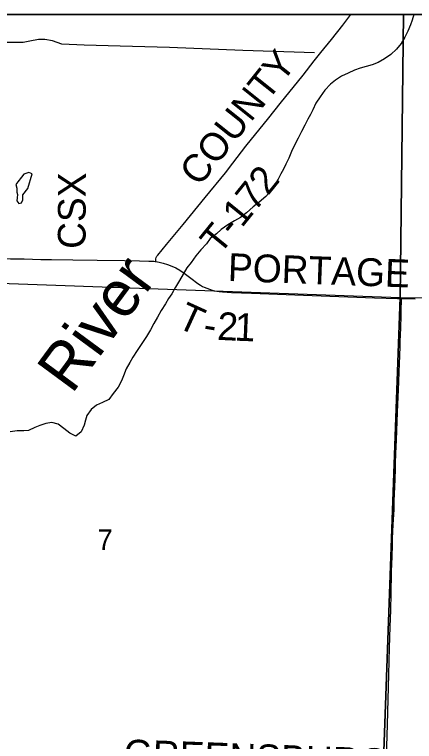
# Model space of a CAD drawing. Extents: x 0 to 39.4, y 0 to 22.
# Drawn here: x 5.679 to 6.495, y 19.416 to 20.9 of the extents above; entities that cross this region are included whole.
import ezdxf

# ---------------------------------------------------------------- set-up
doc = ezdxf.new("R2010")
doc.units = 0
for name, color, linetype in [('Default', 7, 'Continuous'), ('GM_X_Interstate_Route', 7, 'Continuous'), ('GM_X_Major_River', 7, 'Continuous'), ('GM_X_Minor_Lake', 7, 'Continuous'), ('GM_X_Minor_River', 7, 'Continuous'), ('GM_X_Minor_River_Text', 7, 'Continuous'), ('GM_X_Rail_Line_Text', 7, 'Continuous'), ('GM_X_Section', 7, 'Continuous'), ('GM_X_Section_Text', 7, 'Continuous'), ('GM_X_Township_Road', 7, 'Continuous'), ('GM_X_Township_Road_Text', 7, 'Continuous'), ('SH_Data', 7, 'Continuous')]:
    doc.layers.add(name, color=color, linetype=linetype)

msp = doc.modelspace()

# ---------------------------------------------------------------- linework, layer by layer
at = {"layer": 'Default'}
for points in [[(6.4727, 20.9), (5.4307, 20.9), (5.4199, 20.4099), (5.4196, 20.3595), (6.4661, 20.3227)], [(7.4771, 20.9), (6.4727, 20.9), (6.4661, 20.3227), (7.4647, 20.3092)]]:
    msp.add_lwpolyline(points, close=True, dxfattribs=at)
at = {"layer": 'GM_X_Interstate_Route'}
msp.add_lwpolyline([(8.9, 20.9), (5.4327, 20.9)], dxfattribs=at)
at = {"layer": 'GM_X_Major_River'}
for points in [[(6.494, 20.9), (6.4907, 20.8888), (6.4873, 20.8793), (6.4819, 20.866), (6.4758, 20.8539), (6.4682, 20.841), (6.4587, 20.8292), (6.4473, 20.8186), (6.4343, 20.8095), (6.4214, 20.8024), (6.4093, 20.7975), (6.3971, 20.7941), (6.3846, 20.7907), (6.3728, 20.7866), (6.3599, 20.7805), (6.3462, 20.7741), (6.334, 20.7658), (6.3238, 20.7578), (6.3124, 20.7453), (6.3028, 20.7321), (6.2941, 20.7192), (6.2879, 20.7055), (6.2834, 20.696), (6.278, 20.6865), (6.2712, 20.674), (6.2647, 20.6615), (6.2578, 20.6475), (6.2505, 20.6334), (6.244, 20.6202), (6.2387, 20.6065), (6.233, 20.5944), (6.228, 20.5845), (6.2227, 20.5746), (6.2169, 20.564), (6.2093, 20.5519), (6.2032, 20.5417), (6.1922, 20.5284), (6.1781, 20.517), (6.1663, 20.5072), (6.1522, 20.4955), (6.14, 20.486), (6.1279, 20.4788), (6.1142, 20.4709), (6.1009, 20.4614), (6.0914, 20.4527), (6.0781, 20.4429), (6.0704, 20.4319), (6.0594, 20.4198), (6.0491, 20.4073), (6.0392, 20.394), (6.0308, 20.383), (6.0232, 20.3697), (6.0156, 20.3568), (6.0076, 20.3436), (5.9999, 20.3299), (5.9931, 20.3201), (5.987, 20.3094), (5.9778, 20.2962), (5.9706, 20.2825), (5.9633, 20.2692), (5.9564, 20.2567), (5.9481, 20.2431), (5.9385, 20.2287), (5.929, 20.2143), (5.9202, 20.2006), (5.9141, 20.19), (5.9065, 20.1771), (5.9011, 20.1623), (5.8969, 20.1525), (5.8901, 20.1396), (5.8802, 20.1267), (5.871, 20.1145), (5.8585, 20.1081), (5.8463, 20.1028)], [(5.8463, 20.1028), (5.8353, 20.0941), (5.8265, 20.0813), (5.8234, 20.0718), (5.8211, 20.0615), (5.815, 20.0482), (5.804, 20.0395), (5.7915, 20.0453), (5.7794, 20.0548), (5.7676, 20.064), (5.7548, 20.0674), (5.7426, 20.0652), (5.7301, 20.061), (5.7202, 20.0569), (5.7073, 20.0508), (5.6978, 20.0505), (5.6841, 20.0502), (5.6701, 20.0479)]]:
    msp.add_lwpolyline(points, dxfattribs=at)
at = {"layer": 'GM_X_Minor_Lake'}
msp.add_line((5.6834, 20.5371), (5.6845, 20.5325), dxfattribs=at)
msp.add_lwpolyline([(5.6845, 20.5325), (5.6841, 20.5257), (5.6837, 20.52), (5.6875, 20.5143), (5.6928, 20.5158), (5.6959, 20.5215), (5.6959, 20.5321), (5.7058, 20.545), (5.7146, 20.5746), (5.7078, 20.5773), (5.6979, 20.5739), (5.693, 20.5678), (5.6857, 20.5584), (5.6815, 20.5531), (5.6834, 20.5458), (5.6834, 20.5371)], dxfattribs=at)
at = {"layer": 'GM_X_Minor_River'}
msp.add_lwpolyline([(6.291, 20.8217), (6.1449, 20.8264), (5.9954, 20.8329), (5.8941, 20.8354), (5.8209, 20.8376), (5.7754, 20.8392), (5.7655, 20.8427), (5.756, 20.8465), (5.7405, 20.8492), (5.7276, 20.8488), (5.7097, 20.8455), (5.6961, 20.8429), (5.6767, 20.8429), (5.6574, 20.843), (5.6471, 20.8472), (5.6142, 20.8568), (5.5831, 20.8607), (5.5531, 20.8592), (5.5083, 20.8616), (5.4541, 20.8614)], dxfattribs=at)
at = {"layer": 'GM_X_Section'}
for points in [[(5.4196, 20.3595), (6.4661, 20.3227), (6.4302, 19.3208), (5.4065, 19.3604), (5.4059, 19.4006)], [(6.4661, 20.3227), (7.4647, 20.3092), (7.439, 19.3083), (6.4302, 19.3208)]]:
    msp.add_lwpolyline(points, close=True, dxfattribs=at)
at = {"layer": 'GM_X_Township_Road'}
msp.add_line((6.469, 20.3205), (6.4968, 20.3199), dxfattribs=at)
for points in [[(5.967, 20.3961), (5.9672, 20.3995), (5.9675, 20.4016), (5.9682, 20.4039), (5.9695, 20.4066), (5.9714, 20.4091), (5.9891, 20.4307), (6.0228, 20.4713), (6.0683, 20.5264), (6.1092, 20.5772), (6.1245, 20.5968), (6.1513, 20.631), (6.198, 20.6891), (6.2213, 20.7181), (6.2678, 20.7764), (6.2909, 20.8057), (6.3044, 20.8227), (6.3258, 20.8493), (6.3488, 20.8786), (6.3657, 20.9)], [(5.5479, 20.4032), (5.5743, 20.4028), (5.6115, 20.4022), (5.6394, 20.4019), (5.6704, 20.4014), (5.6983, 20.4011), (5.7324, 20.4002), (5.7541, 20.3999), (5.7976, 20.3994), (5.8472, 20.3987), (5.903, 20.398), (5.934, 20.3972), (5.9528, 20.3969)], [(5.9528, 20.3969), (5.9588, 20.3969), (5.9632, 20.3966), (5.9661, 20.3962), (5.967, 20.3961)], [(5.967, 20.3961), (5.9704, 20.3955), (5.9742, 20.3946), (5.9819, 20.3924), (5.9909, 20.3898), (5.9997, 20.3865), (6.0083, 20.3827), (6.0165, 20.3781), (6.0252, 20.3721), (6.0386, 20.3621), (6.0529, 20.3512), (6.0585, 20.3474), (6.0627, 20.345), (6.0657, 20.3435), (6.0712, 20.3412), (6.0766, 20.3391), (6.0821, 20.3375), (6.088, 20.3359), (6.0916, 20.3353), (6.0966, 20.3346), (6.1033, 20.334), (6.1219, 20.3329), (6.1623, 20.3314), (6.2865, 20.3265), (6.4139, 20.3219), (6.4605, 20.3207), (6.469, 20.3205)], [(6.4505, 19.8203), (6.4508, 19.8308), (6.4522, 19.8588), (6.4537, 19.8898), (6.4543, 19.9078), (6.4547, 19.9208), (6.4557, 19.9512), (6.4565, 19.9736), (6.4568, 19.9829), (6.4576, 20.0047), (6.4587, 20.0314), (6.4603, 20.0698), (6.4616, 20.1046), (6.4622, 20.1189), (6.4633, 20.15), (6.4641, 20.1711), (6.4653, 20.2034), (6.4655, 20.2083), (6.4659, 20.2183), (6.4665, 20.2363), (6.4667, 20.2437), (6.4681, 20.2828), (6.4686, 20.3027), (6.4688, 20.3108), (6.4689, 20.3174), (6.469, 20.3205)], [(6.4367, 19.3224), (6.4371, 19.3393), (6.4401, 19.451), (6.4428, 19.553), (6.4445, 19.6076), (6.4458, 19.65), (6.4469, 19.6842), (6.4478, 19.7184), (6.4487, 19.7607), (6.4492, 19.7806), (6.4497, 19.7911), (6.4505, 19.8203)]]:
    msp.add_lwpolyline(points, dxfattribs=at)
at = {"layer": 'SH_Data'}
msp.add_line((2.1, 20.9), (8.9, 20.9), dxfattribs=at)

# ---------------------------------------------------------------- texts
at = {"layer": 'GM_X_Minor_River_Text'}
msp.add_text('River', height=0.09475, rotation=53.6285, dxfattribs=at).set_placement((5.7956, 20.1233))
at = {"layer": 'GM_X_Rail_Line_Text'}
msp.add_text('CSX', height=0.05663, rotation=89.7349, dxfattribs=at).set_placement((5.8237, 20.4216))
at = {"layer": 'GM_X_Section_Text'}
msp.add_text('7', height=0.0419, rotation=0, dxfattribs=at).set_placement((5.848, 19.807))
at = {"layer": 'GM_X_Township_Road_Text'}
for s, height, rotation, p in [('COUNTY', 0.05682, 51.4175, (6.0559, 20.547)), ('T-172', 0.05682, 50.9458, (6.0976, 20.4075)), ('PORTAGE', 0.05682, 357.9285, (6.1137, 20.3562)), ('T', 0.0568, 335.4574, (6.0073, 20.263)), ('2', 0.0568, 357.2918, (6.0918, 20.2361)), ('1', 0.0568, 357.7664, (6.1273, 20.2344)), ('-', 0.0568, 350.7694, (6.0618, 20.2405)), ('GREENSBURG', 0.05682, 357.9544, (5.9009, 19.3638))]:
    msp.add_text(s, height=height, rotation=rotation, dxfattribs=at).set_placement(p)

doc.saveas('drawing.dxf')
